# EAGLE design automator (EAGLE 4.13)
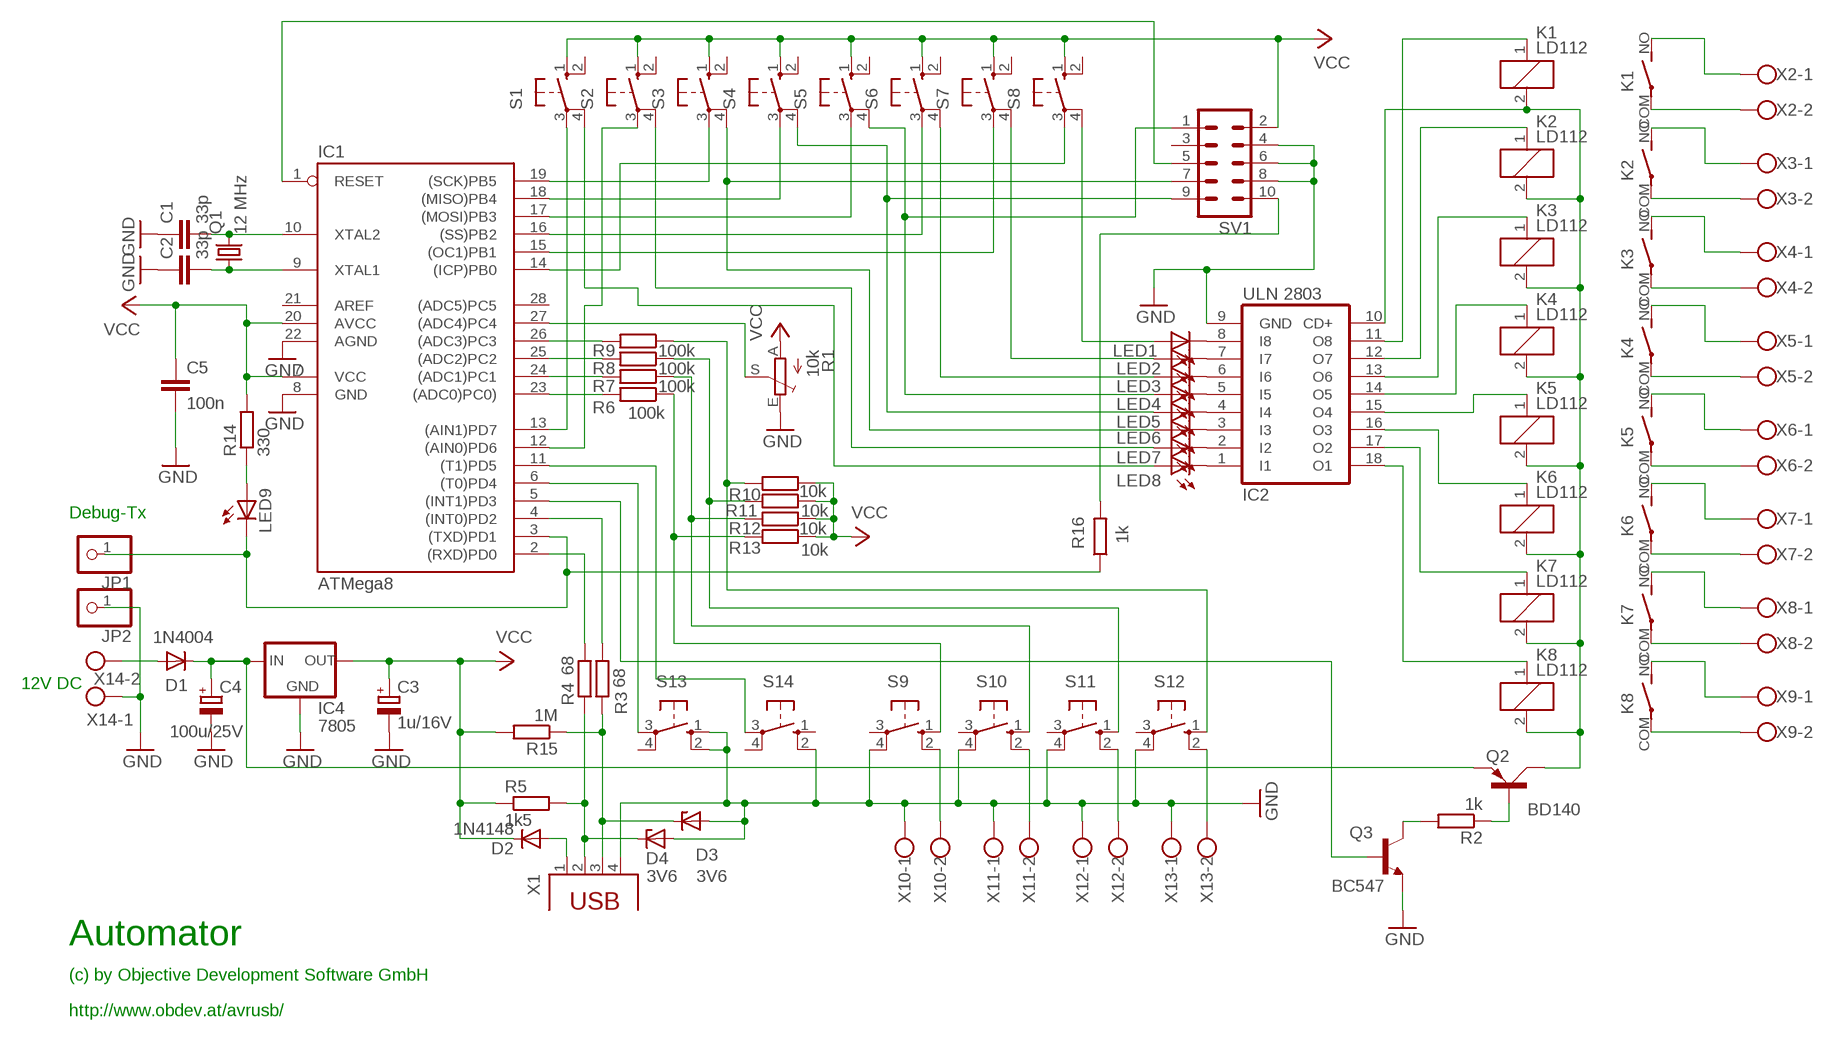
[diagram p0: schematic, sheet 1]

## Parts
C1  33p  C-EU025-024X044  [C025-024X044]
C2  33p  C-EU025-024X044  [C025-024X044]
C3  1u/16V  CPOL-EUE2.5-6  [E2,5-6]
C4  100u/25V  CPOL-EUE2.5-6  [E2,5-6]
C5  100n  C-EU050-025X075  [C050-025X075]
D1  1N4004  [DO41-10]
D2  1N4148  [DO35-10]
D3  3V6  ZENER-DIODEDO34-7  [DO34Z7]
D4  3V6  ZENER-DIODEDO34-7  [DO34Z7]
IC1  ATMega8  AT90S4433P  [DIL28-3]
IC2  ULN 2803  ULN2803A  [DIL18]
IC4  7805  78XXS  [78XXS]
JP1  PINHD-1X1  [1X01]
JP2  PINHD-1X1  [1X01]
K1  LD112  [LD]
K2  LD112  [LD]
K3  LD112  [LD]
K4  LD112  [LD]
K5  LD112  [LD]
K6  LD112  [LD]
K7  LD112  [LD]
K8  LD112  [LD]
LED1  LED3MM  [LED3MM]
LED2  LED3MM  [LED3MM]
LED3  LED3MM  [LED3MM]
LED4  LED3MM  [LED3MM]
LED5  LED3MM  [LED3MM]
LED6  LED3MM  [LED3MM]
LED7  LED3MM  [LED3MM]
LED8  LED3MM  [LED3MM]
LED9  LED3MM  [LED3MM]
Q1  12 MHz  CRYTALHC49S  [HC49/S]
Q2  BD140  [TO126AV]
Q3  BC547  [TO92]
R1  10k  TRIM_EU-CA6V  [CA6V]
R2  1k  R-EU_0207/10  [0207/10]
R3  68  R-EU_0207/10  [0207/10]
R4  68  R-EU_0207/10  [0207/10]
R5  1k5  R-EU_0207/10  [0207/10]
R6  100k  R-EU_0207/10  [0207/10]
R7  100k  R-EU_0207/10  [0207/10]
R8  100k  R-EU_0207/10  [0207/10]
R9  100k  R-EU_0207/10  [0207/10]
R10  10k  R-EU_0207/10  [0207/10]
R11  10k  R-EU_0207/10  [0207/10]
R12  10k  R-EU_0207/10  [0207/10]
R13  10k  R-EU_0207/10  [0207/10]
R14  330  R-EU_0207/10  [0207/10]
R15  1M  R-EU_0207/10  [0207/10]
R16  1k  R-EU_0207/10  [0207/10]
S1  10-XX  [B3F-10XX]
S2  10-XX  [B3F-10XX]
S3  10-XX  [B3F-10XX]
S4  10-XX  [B3F-10XX]
S5  10-XX  [B3F-10XX]
S6  10-XX  [B3F-10XX]
S7  10-XX  [B3F-10XX]
S8  10-XX  [B3F-10XX]
S9  10-XX  [B3F-10XX]
S10  10-XX  [B3F-10XX]
S11  10-XX  [B3F-10XX]
S12  10-XX  [B3F-10XX]
S13  10-XX  [B3F-10XX]
S14  10-XX  [B3F-10XX]
SV1  ML10  [ML10]
X1  PN61729  [PN61729]
X2  W237-102  [W237-102]
X3  W237-102  [W237-102]
X4  W237-102  [W237-102]
X5  W237-102  [W237-102]
X6  W237-102  [W237-102]
X7  W237-102  [W237-102]
X8  W237-102  [W237-102]
X9  W237-102  [W237-102]
X10  W237-102  [W237-102]
X11  W237-102  [W237-102]
X12  W237-102  [W237-102]
X13  W237-102  [W237-102]
X14  W237-102  [W237-102]

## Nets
GND: C1.1 C2.1 C3.- C4.- C5.2 D3.A D4.A IC1.8(GND) IC1.22(AGND) IC2.9(GND) IC4.GND JP2.1 Q3.1(E) R1.E S9.4(P1) S10.4(P1) S11.4(P1) S12.4(P1) S13.1(S) S13.2(S1) S14.2(S1) SV1.4 SV1.6 SV1.8 X1.4 X10.1 X11.1 X12.1 X13.1 X14.1
N$1: C1.2 IC1.10(XTAL2) Q1.2
N$2: C2.2 IC1.9(XTAL1) Q1.1
N$3: D1.A X14.2
N$4: C4.+ D1.C IC4.IN Q2.E
N$5: LED8.A S1.4(P1)
N$6: IC1.27((ADC4)PC4) R1.S
N$7: LED7.A S2.4(P1)
N$8: LED6.A S3.4(P1) SV1.7
N$9: LED5.A S4.4(P1) SV1.9
N$10: IC1.13((AIN1)PD7) S1.3(P)
N$11: IC1.12((AIN0)PD6) S2.3(P)
N$12: IC1.19((SCK)PB5) S3.3(P)
N$13: IC1.18((MISO)PB4) S4.3(P)
N$14: IC2.8(I8) LED1.K(C)
N$15: IC2.7(I7) LED2.K(C)
N$16: IC2.6(I6) LED3.K(C)
N$17: IC2.5(I5) LED4.K(C)
N$18: IC2.4(I4) LED5.K(C)
N$19: IC2.3(I3) LED6.K(C)
N$20: IC2.2(I2) LED7.K(C)
N$21: IC2.1(I1) LED8.K(C)
N$22: IC1.17((MOSI)PB3) S5.3(P)
N$23: IC1.16((SS)PB2) S6.3(P)
N$24: IC1.15((OC1)PB1) S7.3(P)
N$25: IC1.14((ICP)PB0) S8.3(P)
N$26: LED4.A S5.4(P1) SV1.1
N$27: LED3.A S6.4(P1)
N$28: LED2.A S7.4(P1)
N$29: LED1.A S8.4(P1)
N$30: IC2.10(CD+) K1.2 K2.2 K3.2 K4.2 K5.2 K6.2 K7.2 K8.2 Q2.C
N$31: IC2.18(O1) K8.1
N$32: IC2.17(O2) K7.1
N$33: IC2.16(O3) K6.1
N$34: IC2.11(O8) K1.1
N$35: D2.A X1.1
N$36: IC2.12(O7) K2.1
N$37: IC2.13(O6) K3.1
N$38: IC2.14(O5) K4.1
N$39: Q3.3(C) R2.2
N$40: Q2.B R2.1
N$41: S9.2(S1) X10.2
N$42: S10.2(S1) X11.2
N$43: S11.2(S1) X12.2
N$44: S12.2(S1) X13.2
N$45: D4.C R4.1 R5.2 X1.2
N$46: D3.C R3.1 R15.1 X1.3
N$47: IC1.23((ADC0)PC0)) R6.2
N$48: IC1.2((RXD)PD0) R4.2
N$49: IC1.4((INT0)PD2) R3.2
N$50: IC1.24((ADC1)PC1) R7.2
N$51: IC1.25((ADC2)PC2) R8.2
N$52: IC1.26((ADC3)PC3) R9.2
N$53: R6.1 R13.2 S9.1(S)
N$54: R7.1 R12.2 S10.1(S)
N$55: R8.1 R11.2 S11.1(S)
N$56: R9.1 R10.2 S12.1(S)
N$57: IC1.3((TXD)PD1) JP1.1 LED9.K(C) R16.1
N$58: IC1.5((INT1)PD3) Q3.2(B)
N$59: IC1.6((T0)PD4) S13.3(P)
N$60: IC1.11((T1)PD5) S14.3(P)
N$61: LED9.A R14.1
N$62: K8.COM(2:P) X9.2
N$63: K7.COM(2:P) X8.2
N$64: K6.COM(2:P) X7.2
N$65: K5.COM(2:P) X6.2
N$66: K4.COM(2:P) X5.2
N$67: K3.COM(2:P) X4.2
N$68: K2.COM(2:P) X3.2
N$69: K1.COM(2:P) X2.2
N$70: K8.NO(2:S) X9.1
N$71: K7.NO(2:S) X8.1
N$72: K6.NO(2:S) X7.1
N$73: K5.NO(2:S) X6.1
N$74: K4.NO(2:S) X5.1
N$75: K3.NO(2:S) X4.1
N$76: K2.NO(2:S) X3.1
N$77: K1.NO(2:S) X2.1
N$78: IC2.15(O4) K5.1
N$81: IC1.1(RESET) SV1.5
N$83: R16.2 SV1.10
VCC: C3.+ C5.1 D2.C IC1.7(VCC) IC1.20(AVCC) IC4.OUT R1.A R5.1 R10.1 R11.1 R12.1 R13.1 R14.2 R15.2 S1.1(S) S2.1(S) S3.1(S) S4.1(S) S5.1(S) S6.1(S) S7.1(S) S8.1(S) SV1.2
Unconnected: IC1.28((ADC5)PC5) S1.2(S1) S2.2(S1) S3.2(S1) S4.2(S1) S5.2(S1) S6.2(S1) S7.2(S1) S8.2(S1) S9.3(P) S10.3(P) S11.3(P) S12.3(P) S13.4(P1) S14.1(S) S14.4(P1) SV1.3

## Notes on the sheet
- Debug-Tx
- 12V DC
- Automator
- (c) by Objective Development Software GmbH
- http://www.obdev.at/avrusb/

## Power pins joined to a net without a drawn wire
AREF: IC1.21(AREF)

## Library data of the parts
C1 C2 C5 = rcl:C-EU: CAPACITOR, European symbol
C3 C4 = rcl:CPOL-EU: POLARIZED CAPACITOR, European symbol
D1 = diode:1N4004: DIODE
D2 = diode:1N4148: DIODE
D3 D4 = diode:ZENER-DIODE: Z-Diode
IC1 = atmel:AT90S4433: MICROCONTROLLER 4 Kbytes FLASH 128 bytes SRAM 256 bytes EEPROM UART 6-channel 10 bit ADC
IC2 = uln-udn:ULN2803A: DRIVER ARRAY
IC4 = v-reg:78XXS: VOLTAGE REGULATOR
JP1 JP2 = pinhead:PINHD-1X1: PIN HEADER
K1-K8 = relay:LD?*: Slim Power Relay NAiS Source: http://www.mew-europe.com/.. en_ds_61112_0000.pdf
LED1-LED9 = led:LED: LED
Q1 = crystal:CRYTAL: CRYSTAL
Q2 = transistor-power:BD140: PNP TRANSISTOR
Q3 = transistor-npn:BC547*: NPN Transistor
R1 = pot:TRIM_EU-: POTENTIOMETER
R2-R16 = rcl:R-EU_: RESISTOR, European symbol
S1-S14 = switch-omron:10-XX: OMRON SWITCH
SV1 = con-harting-ml:ML10: HARTING
X1 = con-berg:PN61729: BERG USB connector
X2-X14 = con-wago-500:W237-102: WAGO SCREW CLAMP

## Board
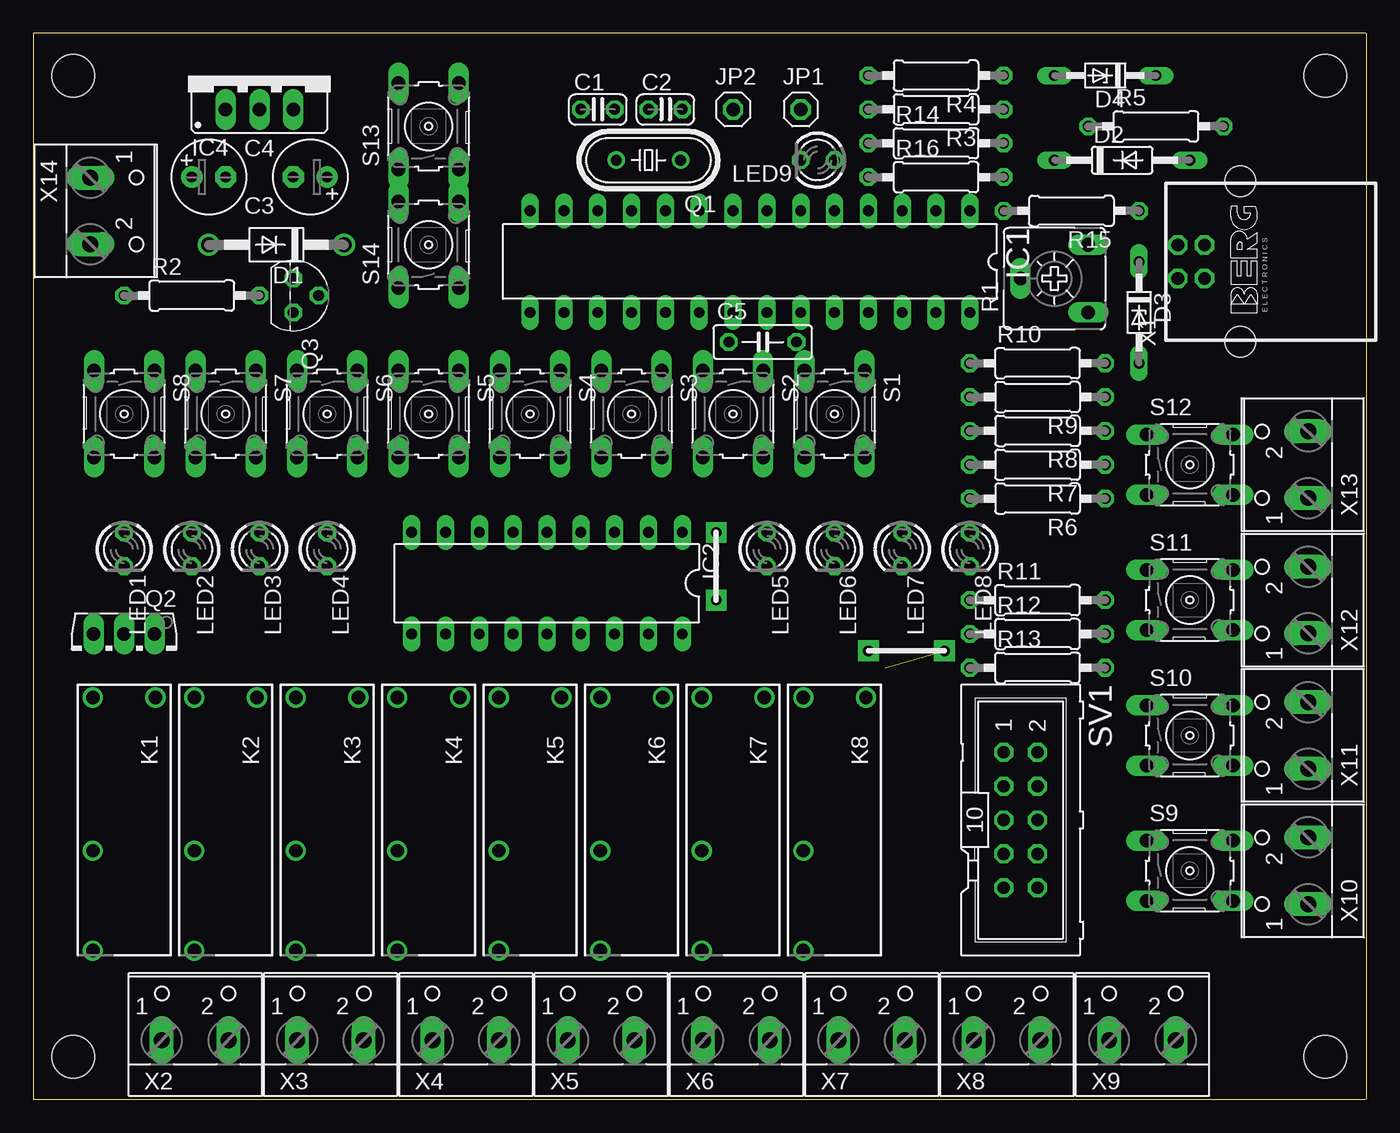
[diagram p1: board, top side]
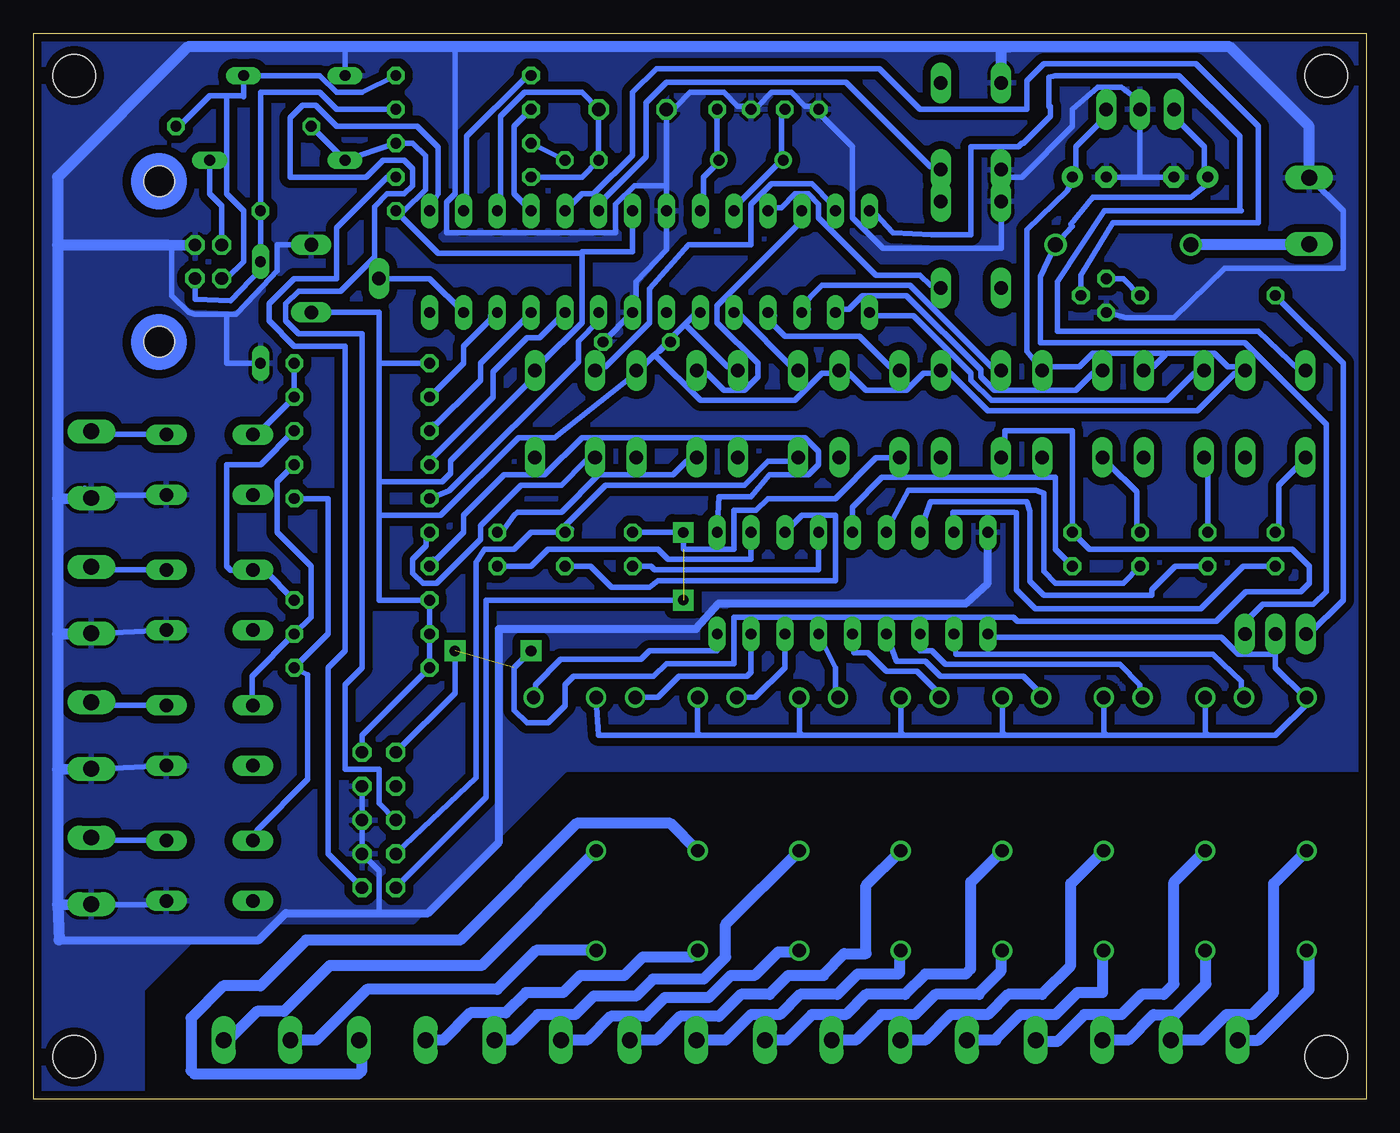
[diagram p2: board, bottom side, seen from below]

Size 100.08 x 80 mm. Coordinates in mm from the lower left corner, seen from the top.
Outline: 100,0 0,0 0,80 100,80
Outline: 100.08,80 100.08,0
Copper layers 16: Bottom 0.035mm
Design rules "default": minimum track width 16mil, minimum drill 31mil, track to track 8mil, track to pad 8mil, pad to pad 8mil, via to via 12mil, smd to smd 8mil, copper to edge 20mil, drill to drill 8mil, minimum pad ring 10mil, minimum via ring 15mil, stop-mask expansion 4mil, vias tented up to drill 0mil, thermal gap 10mil
Holes 3.2 mm at 3.01,3.17 96.99,3.17 96.99,76.83 3.01,76.83

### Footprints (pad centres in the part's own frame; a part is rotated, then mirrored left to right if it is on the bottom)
C025-024X044 = drill 0.813 octagon: 1 -1.27,0; 2 1.27,0
E2,5-6 = drill 0.813 pad 1.6 round: + -1.27,0 | drill 0.813 pad 1.6 octagon: - 1.27,0
C050-025X075 = drill 0.813 octagon: 1 -2.54,0; 2 2.54,0
DO41-10 = drill 1.118 round: A 5.08,0; C -5.08,0
DO35-10 = drill 0.813 long: A 5.08,0; C -5.08,0
DO34Z7 = drill 0.813 long: A 3.81,0; C -3.81,0
DIL28-3 = drill 0.813 long: 1 -16.51,-3.81; 2 -13.97,-3.81; 3 -11.43,-3.81; 4 -8.89,-3.81; 5 -6.35,-3.81; 6 -3.81,-3.81; 7 -1.27,-3.81; 8 1.27,-3.81; 9 3.81,-3.81; 10 6.35,-3.81; 11 8.89,-3.81; 12 11.43,-3.81; 13 13.97,-3.81; 14 16.51,-3.81; 15 16.51,3.81; 16 13.97,3.81; 17 11.43,3.81; 18 8.89,3.81; 19 6.35,3.81; 20 3.81,3.81; 21 1.27,3.81; 22 -1.27,3.81; 23 -3.81,3.81; 24 -6.35,3.81; 25 -8.89,3.81; 26 -11.43,3.81; 27 -13.97,3.81; 28 -16.51,3.81
DIL18 = drill 0.813 long: 1 -10.16,-3.81; 2 -7.62,-3.81; 3 -5.08,-3.81; 4 -2.54,-3.81; 5 0,-3.81; 6 2.54,-3.81; 7 5.08,-3.81; 8 7.62,-3.81; 9 10.16,-3.81; 10 10.16,3.81; 11 7.62,3.81; 12 5.08,3.81; 13 2.54,3.81; 14 0,3.81; 15 -2.54,3.81; 16 -5.08,3.81; 17 -7.62,3.81; 18 -10.16,3.81
78XXS = drill 1.016 long: GND 0,-2.54; IN -2.54,-2.54; OUT 2.54,-2.54
1X01 = drill 1.016 octagon: 1 0,0
LD = drill 1 round: 1 -9.2,2.35; 2 -9.2,-2.35; COM 2.3,-2.35; NO 9.8,-2.35
LED3MM = drill 0.813 octagon: A -1.27,0; K 1.27,0
HC49/S = drill 0.813 round: 1 -2.413,0; 2 2.413,0
TO126AV = drill 1.016 long: B 2.286,-1.27; C 0,-1.27; E -2.286,-1.27
TO92 = drill 0.813 octagon: 1 1.27,0; 2 0,1.905; 3 -1.27,0
CA6V = drill 1.016 long: A -2.54,-2.54; E 2.54,-2.54; S 0,2.54
0207/10 = drill 0.813 octagon: 1 -5.08,0; 2 5.08,0
B3F-10XX = drill 1.016 long: 1 -3.251,2.261; 2 3.251,2.261; 3 -3.251,-2.261; 4 3.251,-2.261
ML10 = drill 0.914 octagon: 1 -5.08,-1.27; 2 -5.08,1.27; 3 -2.54,-1.27; 4 -2.54,1.27; 5 0,-1.27; 6 0,1.27; 7 2.54,-1.27; 8 2.54,1.27; 9 5.08,-1.27; 10 5.08,1.27
PN61729 = drill 0.95 octagon: 1 1.25,4.71; 2 -1.25,4.71; 3 -1.25,2.71; 4 1.25,2.71 | hole 2.3: -6.02,0; 6.02,0
W237-102 = drill 1.194 long: 1 -2.5,-1.27; 2 2.5,-1.27

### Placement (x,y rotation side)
C1  42.38,74.29 0 top
C2  47.46,74.29 0 top
C3  20.79,69.21 180 top
C4  13.17,69.21 0 top
C5  54.76,56.83 0 top
D1  18.25,64.13 180 top
D2  81.75,70.48 0 top
D3  83.02,59.05 270 top
D4  80.48,76.83 180 top
IC1  53.81,62.86 180 top
IC2  38.57,38.73 180 top
IC4  16.98,76.83 0 top
JP1  57.62,74.29 0 top
JP2  52.54,74.29 0 top
K1  6.82,20.95 270 top
K2  14.44,20.95 270 top
K3  22.06,20.95 270 top
K4  29.68,20.95 270 top
K5  37.3,20.95 270 top
K6  44.92,20.95 270 top
K7  52.54,20.95 270 top
K8  60.16,20.95 270 top
LED1  6.82,41.27 270 top
LED2  11.9,41.27 270 top
LED3  16.98,41.27 270 top
LED4  22.06,41.27 270 top
LED5  55.08,41.27 270 top
LED6  60.16,41.27 270 top
LED7  65.24,41.27 270 top
LED8  70.32,41.27 270 top
LED9  58.89,70.48 180 top
Q1  46.19,70.48 180 top
Q2  6.82,33.65 180 top
Q3  19.52,60.32 270 top
R1  76.67,61.59 90 top
R2  11.9,60.32 0 top
R3  67.78,74.29 180 top
R4  67.78,76.83 180 top
R5  84.29,73.02 0 top
R6  75.4,45.08 180 top
R7  75.4,47.62 180 top
R8  75.4,50.16 180 top
R9  75.4,52.7 180 top
R10  75.4,55.24 0 top
R11  75.4,37.46 0 top
R12  75.4,34.92 0 top
R13  75.4,32.38 0 top
R14  67.78,71.75 0 top
R15  77.94,66.67 180 top
R16  67.78,69.21 0 top
S1  60.16,51.43 270 top
S2  52.54,51.43 270 top
S3  44.92,51.43 270 top
S4  37.3,51.43 270 top
S5  29.68,51.43 270 top
S6  22.06,51.43 270 top
S7  14.44,51.43 270 top
S8  6.82,51.43 270 top
S9  86.83,17.14 0 top
S10  86.83,27.3 0 top
S11  86.83,37.46 0 top
S12  86.83,47.62 0 top
S13  29.68,73.02 90 top
S14  29.68,64.13 90 top
SV1  74.13,20.95 270 top
X1  90.64,62.86 90 top
X2  12.15,5.71 0 top
X3  22.31,5.71 0 top
X4  32.47,5.71 0 top
X5  42.63,5.71 0 top
X6  52.79,5.71 0 top
X7  62.95,5.71 0 top
X8  73.11,5.71 0 top
X9  83.27,5.71 0 top
X10  94.45,17.14 90 top
X11  94.45,27.3 90 top
X12  94.45,37.46 90 top
X13  94.45,47.62 90 top
X14  5.55,66.67 270 top

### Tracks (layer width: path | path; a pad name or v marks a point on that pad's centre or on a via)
GND
  Bottom 0.406: 16.98,69.21 C4.- | 16.98,69.21 C3.- | 16.98,69.21 IC4.GND 16.47,74.54 18.38,75.94 20.15,75.94 22.06,74.29 22.06,73.02 25.87,69.21 27.14,69.21 | S12.4 90.64,45.33 94.96,45.33 X13.1 96.23,45.84 | X10.1 94.96,14.6 90.64,14.6 S9.4 | 27.14,69.21 27.39,68.96 27.39,63.88 36.28,63.88 38.57,66.16 38.57,71.5 40.86,73.78 C1.1 41.62,74.54 42.13,74.54 43.14,75.56 44.67,75.56 45.68,74.54 C2.1 46.7,74.54 47.21,74.54 48.22,75.56 50.76,75.56 51.78,74.54 JP2.1 52.54,68.57 | S13.1 27.42,69.49 27.14,69.21 | S14.2 27.42,68.93 27.14,69.21 | C5.2 IC1.22 54.83,59.56 54.83,61.34 52.54,63.75 IC1.8 52.54,68.57 | Q3.1 18,58.67 14.44,58.67 10.63,62.35 1.74,62.35 1.74,66.67 4.28,69.21 | 52.54,68.57 54.95,68.57 56.35,67.18 56.35,65.02 69.05,65.02 69.05,67.3 68.41,67.94 68.41,78.99 | X11.1 95.72,24.76 S10.4 | X12.1 95.72,34.92 S11.4 | R1.E 81.75,64.13 81.75,62.16 83.44,60.41 84.86,58.92 85.56,58.92 | 76.67,79.05 76.67,78.99 D4.A | 85.56,58.92 87.97,58.92 88.42,59.05 89.69,60.32 89.69,63.81 90,64.13 90,64.11 | SV1.6 SV1.8 74.13,17.14 74.13,13.97 | SV1.6 SV1.4 SV1.6 | D3.A 85.56,55.24 85.56,58.92
  Bottom 0.61: 98.13,11.93 83.15,11.93 81.11,13.97 74.13,13.97 70.45,13.97 65.11,19.3 65.11,35.3 50.32,35.3 48.6,37.21 30.06,37.21 28.41,38.73 IC2.9
  Bottom 0.813: X14.1 4.28,69.21 4.28,73.02 10.25,78.99 26.76,78.99 | 26.76,78.99 68.41,78.99 76.67,78.99 88.48,78.99 98.26,69.21 98.26,64.13 | S13.2 27.42,78.84 26.76,78.99 | 98.26,14.6 X10.1 | 98.26,64.13 98.26,45.08 | 98.26,45.08 98.26,34.92 | 98.26,34.92 98.26,24.76 | 98.26,24.76 98.26,14.6 | 98.26,64.13 90,64.11 X1.4 | 98.26,24.76 X11.1 | 98.26,34.92 95.72,34.92 | 98.26,45.08 X13.1 | 98.26,14.6 98.13,11.93
  pour Bottom (isolate 0.61): 0.47,79.37 99.53,79.37 99.53,0.63 91.91,0.63 91.91,8.25 88.1,12.06 83.02,12.06 81.75,13.33 71.59,13.33 70.32,14.6 60.16,24.76 0.47,24.76
N$1
  Bottom 0.406: C1.2 43.9,73.78 43.9,70.99 Q1.2 44.16,70.23 47.21,67.18 IC1.10
N$2
  Bottom 0.406: C2.2 48.73,70.99 Q1.1 48.98,69.97 49.75,69.21 49.75,67.18 IC1.9
N$3
  Bottom 0.406: X14.2 5.04,64.13
  Bottom 0.813: 5.04,64.13 D1.A
N$4
  Bottom 0.406: IC4.IN 14.19,73.53 12.15,71.5 12.15,69.97 C4.+ 11.9,68.7 13.17,67.69 20.54,67.69 22.19,65.65 22.06,65.53 D1.C 24.47,61.72 24.47,56.76 9.11,56.76 3.01,50.67 3.01,38.73 | 3.01,38.73 3.01,38.22 | Q2.E 9.04,34.98 9.04,35.87 7.77,37.14 3.96,37.14 3.01,38.1 3.01,38.73
N$5
  Bottom 0.406: LED8.A 70.57,42.03 70.57,41.52 71.59,40.51 71.59,39.49 70.83,38.73 69.81,38.73 66.51,42.03 66.51,43.05 63.46,46.1 60.41,46.1 58.64,47.87 S1.4
N$6
  Bottom 0.406: R1.S 70.32,61.59 IC1.27
N$7
  Bottom 0.406: LED7.A 64.73,42.79 63.97,43.81 63.72,44.06 60.41,44.06 57.62,46.86 52.03,46.86 51.02,47.87 S2.4
N$8
  Bottom 0.406: S3.4 43.4,47.87 44.92,47.87 46.7,46.1 57.11,46.1 60.41,42.79 59.65,42.79 LED6.A 62.7,42.54 63.97,41.27 66.19,41.27 66.83,40.32 66.83,24.12 SV1.7
N$9  (1 unrouted)
  Bottom 0.406: LED5.A 51.27,42.54 51.27,41.27 47.46,41.27 47.46,44.19 45.81,44.19 44.92,45.08 39.84,45.08 36.79,48.13 35.09,48.13 S4.4 | SV1.9 66.07,22.66 66.07,37.46 51.27,37.46
N$10
  Bottom 0.406: IC1.13 40.09,67.18 41.62,68.7 44.67,68.7 46.19,67.18 46.19,64.13 50.89,64.13 53.81,60.83 53.81,58.29 57.11,54.99 S1.3
N$11
  Bottom 0.406: IC1.12 42.63,66.16 42.63,65.65 48.73,59.56 48.73,58.29 45.68,55.24 45.68,54.22 46.7,53.21 48.22,53.21 49.49,54.48 S2.3
N$12
  Bottom 0.406: IC1.19 46.95,58.8 43.14,54.99 S3.3
N$13
  Bottom 0.406: IC1.18 44.41,58.8 45.17,58.8 43.65,57.27 38.06,57.27 35.78,54.99 S4.3
N$14
  Bottom 0.406: LED1.K 9.23,40 12.41,36.83 24.85,36.83 26.25,38.22 26.25,44 26.44,44.06 31.01,44.06 30.95,43.05 IC2.8
N$15
  Bottom 0.406: LED2.K 14.31,40 16.09,38.22 16.09,37.84 24.22,37.84 25.23,38.86 25.23,44.13 25.49,44.83 32.73,44.83 IC2.7
N$16
  Bottom 0.406: LED3.K 18.25,38.73 23.33,38.73 24.22,39.62 24.22,45.46 24.79,45.72 34.38,45.72 36.03,42.67 IC2.6
N$17
  Bottom 0.406: LED4.K 23.33,41.27 23.33,46.67 36.35,46.67 38.57,44.45 IC2.5
N$18
  Bottom 0.406: LED5.K 53.68,40 53.43,39.75 41.11,39.75 IC2.4
N$19
  Bottom 0.406: LED6.K 58.25,40 56.67,38.41 53.81,38.41 53.17,38.92 39.84,38.92 39.84,43.81 42.38,43.81 IC2.3
N$20
  Bottom 0.406: LED7.K 62.7,40 61.43,41.27 53.17,41.27 52.41,40.51 46.19,40.51 IC2.2
N$21
  Bottom 0.406: IC2.1 48.6,45.21 46.19,45.21 44.79,46.86 41.87,46.86 41.11,47.62 41.11,48.64 42.13,49.65 58.89,49.65 61.68,46.86 64.73,46.86 67.78,43.81 67.78,42.54 LED8.K 70.07,40.51
N$22
  Bottom 0.406: IC1.17 41.87,59.3 42.63,59.3 40.86,61.08 34.25,61.08 28.16,54.99 S5.3
N$23
  Bottom 0.406: IC1.16 39.33,59.3 38.82,59.3 37.81,60.32 34.51,60.32 28.92,54.73 28.92,54.22 27.9,53.21 21.81,53.21 20.54,54.48 S6.3
N$24
  Bottom 0.406: IC1.15 36.79,58.8 34,58.8 29.68,54.48 29.68,53.97 28.16,52.45 14.95,52.45 12.92,54.48 S7.3
N$25
  Bottom 0.406: IC1.14 36.79,66.42 35.52,65.02 32.6,64.89 29.68,64.89 29.68,71.5 26.12,71.5 25.87,71.75 25.74,71.75 23.71,73.78 23.71,74.42 | 9.49,66.67 9.49,72.26 14.06,76.83 23.33,76.83 23.84,76.7 23.84,74.54 23.71,74.42 | 23.71,74.42 23.71,74.54 | S8.3 4.99,54.68 8.09,57.65 23.2,57.65 23.2,61.34 19.65,66.67 9.49,66.67 | 9.49,66.67 9.36,66.67
N$26  (1 unrouted)
  Bottom 0.406: SV1.1 68.41,30.47 68.41,33.65 | S5.4 27.42,48.22 27.46,48.26 27.14,48.57 27.14,50.16 22.06,50.16 LED4.A 20.79,41.27 5.55,41.27 4.28,40 4.28,38.73 4.92,38.1 9.04,38.1 11.27,35.87 26.19,35.87 26.5,36.19 47.46,36.19 47.46,32.7 52.54,32.7 53.49,31.74 59.52,31.74 60.16,31.11 60.16,29.52 61.43,28.25 63.02,28.25 63.97,29.2 63.97,32.38 62.7,33.65
N$27
  Bottom 0.406: LED3.A 17.23,43.05 17.23,45.59 19.27,47.62 S6.4
N$28
  Bottom 0.406: LED2.A 11.9,47.62 S7.4
N$29
  Bottom 0.406: LED1.A 6.57,43.05 6.57,46.1 5.04,47.62 S8.4
N$30
  Bottom 0.406: K8.2 57.81,30.03 57.62,27.3 50,27.3 | 11.9,27.3 6.82,27.3 4.28,29.84 4.47,30.03 K1.2 4.59,30.15 6.82,32.38 6.82,33.4 | 11.9,27.3 19.52,27.3 | 19.52,27.3 27.14,27.3 | 27.14,27.3 34.76,27.3 | 34.76,27.3 42.38,27.3 | 42.38,27.3 50,27.3 | 6.82,33.4 Q2.C | K2.2 12.09,27.49 11.9,27.3 | K3.2 19.71,27.49 19.52,27.3 | K4.2 27.33,27.49 27.14,27.3 | K5.2 34.95,27.49 34.76,27.3 | K6.2 42.57,27.49 42.38,27.3 | K7.2 50.19,27.49 50,27.3 | 6.82,33.4 9.61,33.4 10.88,34.67 27.9,34.67 IC2.10
N$31
  Bottom 0.406: IC2.18 48.73,33.65 53.81,33.65 54.45,33.02 60.48,33.02 62.38,31.11 62.38,30.16 K8.1
N$32
  Bottom 0.406: IC2.17 46.19,32.06 46.51,31.74 51.59,31.74 53.17,30.16 K7.1
N$33
  Bottom 0.406: IC2.16 43.65,32.38 45.87,30.16 K6.1 | K6.1 47.46,30.16 | K6.1
N$34
  Bottom 0.406: IC2.11 30.82,33.4 11.52,33.4 9.36,31.36 9.36,29.96 | 9.36,29.96 9.36,29.84 | K1.1 9.36,29.96
N$35
  Bottom 0.406: X1.1 85.93,67.04 86.83,67.94 D2.A
N$36
  Bottom 0.406: IC2.12 33.49,33.65 32.6,33.65 31.58,32.63 18.5,32.63 16.98,31.11 16.98,29.96 | 16.98,29.96 16.98,29.84 | K2.1 16.98,29.96
N$37
  Bottom 0.406: IC2.13 35.27,32.89 33.11,32.89 31.97,31.74 25.74,31.74 24.6,30.6 24.6,29.96 | 24.6,29.96 24.6,29.84 | K3.1 24.6,29.96
N$38
  Bottom 0.406: IC2.14 38.44,33.52 37.43,33.52 36.03,32.13 33.74,32.13 32.22,30.6 32.22,30.34 K4.1
N$39
  Bottom 0.406: R2.2 18.25,61.59 Q3.3
N$40
  Bottom 0.406: R2.1 1.74,55.24 1.74,37.46 4.28,34.92 Q2.B
N$41
  Bottom 0.406: S9.2 90.64,19.43 94.96,19.43 X10.2
N$42
  Bottom 0.406: S10.2 90.64,29.59 94.96,29.59 X11.2
N$43
  Bottom 0.406: S11.2 90.64,39.75 94.96,39.75 X12.2
N$44
  Bottom 0.406: S12.2 90.64,49.91 94.96,49.91 X13.2
N$45
  Bottom 0.406: 85.56,75.31 84.29,75.31 | 85.56,75.31 86.83,75.31 88.86,73.27 R5.2 | X1.2 85.54,61.61 84.29,62.86 84.29,66.67 85.56,67.94 85.56,75.31 | 84.29,75.31 84.29,75.24 | 84.29,75.31 D4.C 78.58,76.83 77.3,75.56 75.4,75.56 R4.1
N$46
  Bottom 0.406: X1.3 87.93,60.02 85.24,59.94 83.02,62.29 D3.C R15.1 83.02,75.56 78.58,75.56 77.3,74.29 R3.1
N$47
  Bottom 0.406: R6.2 68.86,45.65 59.14,55.37 59.14,56.89 57.62,58.41 IC1.23
N$48
  Bottom 0.406: IC1.2 67.53,67.18 67.53,72.26 63.21,76.58 R4.2
N$49
  Bottom 0.406: IC1.4 63.97,67.94 63.97,73.02 R3.2
N$50
  Bottom 0.406: R7.2 70.32,47.94 65.56,52.7 65.56,54.61 63.02,57.15 62.06,57.15 IC1.24
N$51
  Bottom 0.406: 70.07,50.67 R8.2 66.51,53.97 66.51,55.24 63.21,58.54 62.95,58.54 IC1.25
N$52
  Bottom 0.406: IC1.26 65.75,58.8 65.75,58.54 67.78,56.51 67.78,55.24 R9.2
N$53
  Bottom 0.406: S9.1 83.27,20.19 79.46,24 79.46,31.87 R13.2 77.94,34.92 77.94,45.08 R6.1
N$54
  Bottom 0.406: S10.1 83.62,29.52 83.66,29.52 83.66,31.74 R12.2 79.21,36.19 79.21,40 81.75,42.54 81.75,46.35 R7.1
N$55
  Bottom 0.406: R11.2 82.7,39.68 83.62,39.68 | R8.1 83.02,47.62 85.56,47.62 85.56,40 85.24,39.68 83.62,39.68 | 83.62,39.68 S11.1
N$56
  Bottom 0.406: R10.2 R9.1 83.34,49.84 83.62,49.84 | 83.62,49.84 83.66,49.84 | S12.1 83.62,49.84
N$57
  Bottom 0.406: IC1.3 64.99,67.18 64.99,73.78 63.21,75.56 58.89,75.56 JP1.1 LED9.K 58.89,69.21 R16.1
N$58
  Bottom 0.406: IC1.5 58.89,67.94 58,67.94 55.08,70.86 55.08,75.56 53.3,77.34 36.54,77.34 33.49,74.29 25.49,74.29 25.49,76.45 24.22,77.72 12.79,77.72 8.09,73.02 8.09,65.78 19.01,65.78 21.42,61.84 Q3.2
N$59
  Bottom 0.406: IC1.6 57.87,66.8 57.62,67.18 54.06,70.73 54.06,74.8 52.54,76.32 39.08,76.32 32.73,69.97 S13.3
N$60
  Bottom 0.406: IC1.11 44.41,66.92 43.9,66.92 42.89,67.94 41.87,67.94 41.11,67.18 41.11,66.16 36.79,61.84 33.49,61.84 32.73,61.08 S14.3
N$61
  Bottom 0.406: LED9.A R14.1
N$62
  Bottom 0.813: K8.COM 66.43,10.03 77.81,10.03 81.24,6.6 83.27,6.6 85.43,4.44 X9.2
N$63
  Bottom 0.813: K7.COM 52.24,20.7 59.27,20.7 68.03,11.93 79.59,11.93 83.02,8.5 85.81,8.5 88.23,6.09 88.23,2.15 87.97,1.9 75.65,1.9 75.4,2.15 75.4,4.44 X8.2
N$64
  Bottom 0.813: K6.COM 48.09,13.12 48.09,10.66 49.75,9.01 53.56,9.01 54.83,7.74 58,7.74 59.4,6.34 62.19,6.34 64.1,4.44 X7.2 65.62,4.44
N$65
  Bottom 0.813: K5.COM 37.55,16.05 37.55,10.92 39.2,10.92 40.73,9.39 40.73,9.27 43.4,9.27 44.79,7.87 46.95,7.87 48.6,6.22 51.52,6.22 53.3,4.44 X6.2
N$66
  Bottom 0.813: K4.COM 29.68,16.3 29.68,9.77 30.06,9.39 33.11,9.39 34.63,7.87 37.55,7.87 39.08,6.34 41.62,6.34 43.52,4.44 X5.2
N$67
  Bottom 0.813: K3.COM 22.19,16.17 22.19,10.03 24.35,7.87 26.89,7.87 28.41,6.34 31.2,6.34 33.11,4.44 X4.2
N$68
  Bottom 0.813: K2.COM 14.44,16.3 14.44,8.63 15.2,7.87 16.85,7.87 18.38,6.34 21.17,6.34 23.2,4.31 24.94,4.31 | 24.94,4.31 24.98,4.31 | 24.94,4.31 X3.2
N$69
  Bottom 0.813: K1.COM 6.95,16.17 6.95,8 8.6,6.34 10.5,6.34 12.41,4.44 X2.2 14.69,4.44
N$70
  Bottom 0.813: K8.NO 57.83,11.17 62.32,11.17 65.24,8.25 75.02,8.25 78.83,4.44 X9.1 80.86,4.44
N$71
  Bottom 0.813: K7.NO 50.68,10.66 54.32,10.66 55.71,9.27 59.02,9.27 60.29,8 63.08,8 64.61,6.47 67.27,6.47 69.3,4.44 X8.1 70.7,4.44
N$72
  Bottom 0.813: K6.NO 42.68,11.04 44.16,11.04 45.94,9.27 47.71,9.27 49.37,7.62 52.67,7.62 54.06,6.22 56.73,6.22 58.51,4.44 X7.1
N$73
  Bottom 0.813: K5.NO 35.01,11.09 35.01,9.52 35.14,9.39 38.19,9.39 39.71,7.87 42.51,7.87 44.03,6.34 46.19,6.34 48.09,4.44 X6.1
N$74
  Bottom 0.813: K4.NO 27.39,11.09 27.39,9.65 29.04,8 29.04,7.87 32.35,7.87 33.87,6.34 36.41,6.34 38.32,4.44 X5.1
N$75
  Bottom 0.813: K3.NO 19.77,11.09 19.77,8 21.68,8 23.33,6.34 26,6.34 27.77,4.57 27.77,4.44 X4.1 30.06,4.44
N$76
  Bottom 0.813: K2.NO 12.03,11.09 12.03,8.63 14.31,6.34 15.96,6.34 17.87,4.44 X3.1
N$77
  Bottom 0.813: K1.NO 4.28,10.96 4.28,8.25 8.09,4.44 X2.1
N$78
  Bottom 0.406: 39.84,29.96 39.84,29.84 | K5.1 39.84,29.96 | IC2.15 39.84,32.38 39.84,29.96
N$79  (via drill 0.8)
  other vias: 51.27,42.54
N$80  (via drill 0.8)
  other vias: 51.27,37.46
N$81
  Bottom 0.406: IC1.1 69.69,67.94 69.69,71.43 71.27,73.02 77.3,73.02 78.89,74.61 79.84,74.61 80.8,73.66 80.8,69.21 75.08,69.21 73.81,70.48 72.22,70.48 71.59,69.84 71.59,68.57 72.22,67.94 73.5,67.94 74.45,66.99 74.45,63.18 76.99,60.64 80.16,60.64 81.11,59.69 81.11,58.41 80.16,57.46 75.4,57.46 75.4,32.38 76.67,31.11 76.67,24.76 74.13,24.76 74.13,22.22 SV1.5
N$82  (via drill 0.8)
  other vias: 62.7,33.65
N$83
  Bottom 0.406: SV1.10 77.94,18.41 77.94,32.38 76.67,33.65 76.67,56.51 80.48,56.51 82.39,58.41 82.39,59.69 80.48,61.59 77.3,61.59 77.3,65.4 73.5,69.21 R16.2
N$84  (via drill 0.8)
  other vias: 68.41,33.65
N$85
  pour Bottom (isolate 0.61): 0.47,79.37 99.53,79.37 99.53,0.63 91.91,0.63 91.91,9.52 89.37,12.06 83.02,12.06 81.75,14.6 70.32,14.6 60.16,24.76 0.47,24.76
VCC
  Bottom 0.406: 53.43,55.88 54.32,54.99 S2.1 54.7,54.48 54.83,54.48 60.92,49.65 63.65,49.65 69.5,43.81 74.13,43.81 | 53.43,55.88 53.11,56.19 | 53.11,56.19 51.14,58.16 | 51.14,58.16 50.51,58.8 IC1.20 | S3.1 47.97,54.99 51.14,58.16 | 53.43,55.88 50,52.45 42.89,52.45 40.86,54.48 40.35,54.48 S4.1 38.82,54.48 37.55,53.21 34.51,53.21 33.24,54.48 32.73,54.48 S5.1 31.2,54.48 28.41,51.68 12.66,51.68 9.87,54.48 S8.1 9.87,54.99 10.38,54.99 11.39,56 14.95,56 15.08,55.88 | 15.08,55.88 15.96,54.99 S7.1 | 15.08,55.88 15.2,56 20.54,56 21.55,54.99 23.58,54.99 S6.1 25.49,56.13 25.49,65.27 22.44,68.19 22.31,68.45 22.06,68.7 C3.+ 21.81,69.97 21.81,71.5 19.77,73.53 IC4.OUT | IC1.7 55.08,63.62 58.89,63.62 58.89,63.5 | 58.89,63.5 58.89,58.29 61.94,55.24 S1.1 62.42,54.25 68.73,47.94 68.73,46.98 69.37,46.35 74.13,46.35 | 74.13,43.81 74.13,46.35 | 74.13,46.35 74.13,55.24 | 74.13,55.24 74.13,55.49 | 53.11,56.19 53.05,56.13 52.67,56.51 C5.1 | R5.1 D2.C R14.2 71.59,71.75 70.64,70.8 70.64,68.26 72.22,66.67 R15.2 69.69,63.5 58.89,63.5 | 74.13,43.81 74.13,37.46 R11.1 R12.1 R13.1 75.4,27.3 SV1.2 | R1.A 74.13,59.05 74.13,55.24 | 74.13,55.24 R10.1
(copper drawn outside any net)
  shapes: Bottom circle x2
